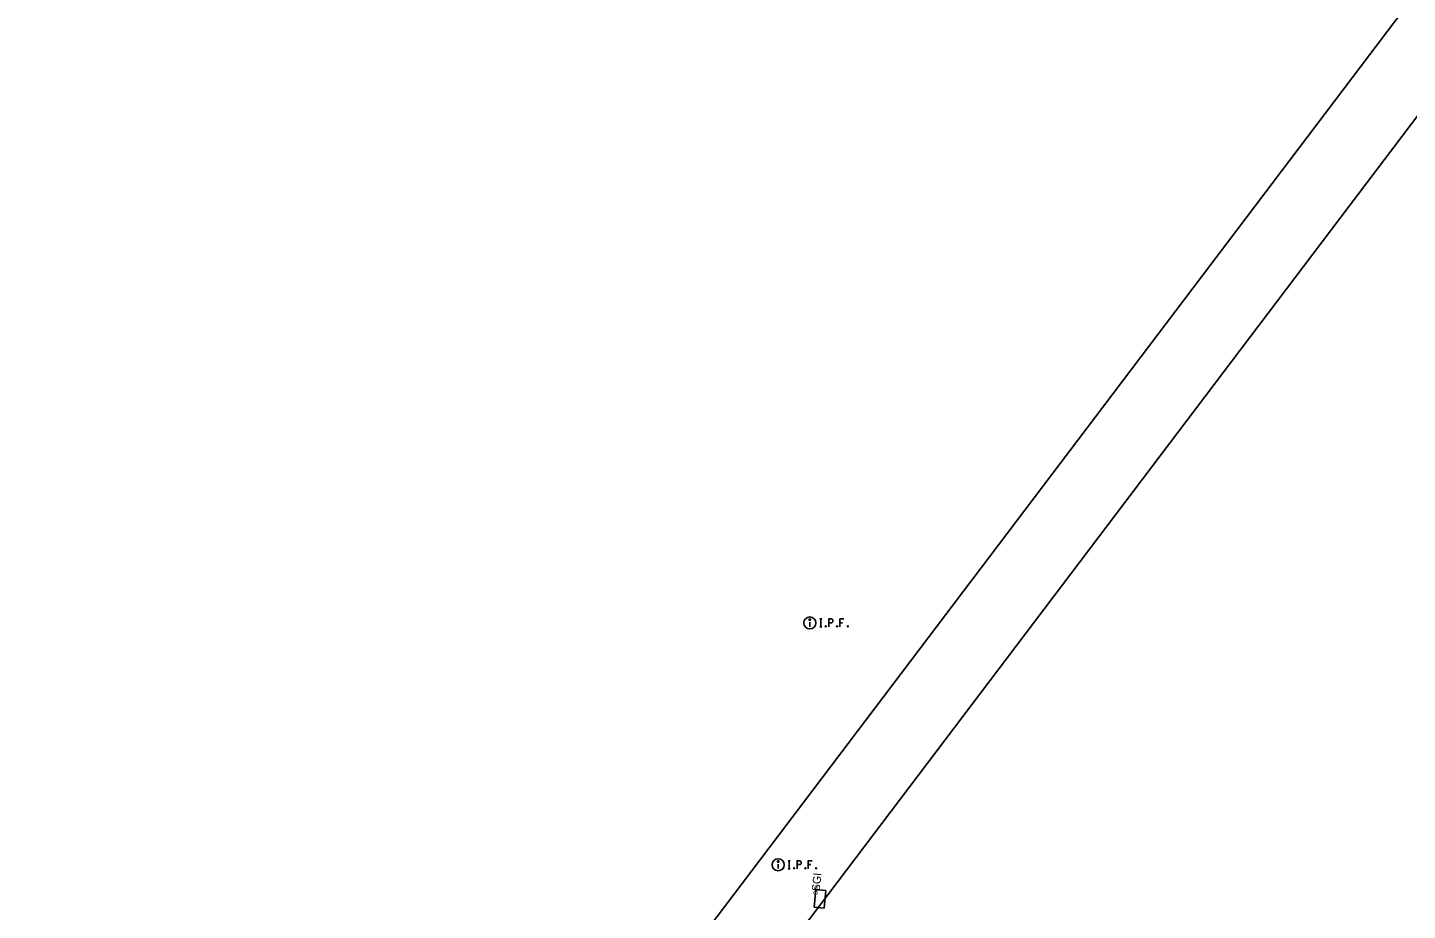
# Model space of a CAD drawing. Extents: x 1363693 to 1365209, y 422201 to 424153.
# Drawn here: x 1364113.8 to 1364389.7, y 423623 to 423799.5 of the extents above; entities that cross this region are included whole.
import ezdxf

# ---------------------------------------------------------------- set-up
doc = ezdxf.new("R2010")
doc.units = 0
for name, color, linetype in [('DR_X_Cells', 7, 'Continuous'), ('DR_X_Storm_Sewer', 7, 'Continuous'), ('DR_X_Text', 7, 'Continuous'), ('SV_X_Mon_Cells_Found', 7, 'Continuous')]:
    doc.layers.add(name, color=color, linetype=linetype)

msp = doc.modelspace()

# ---------------------------------------------------------------- linework, layer by layer
at = {"layer": 'DR_X_Cells'}
for p, q in [((1364271.04, 423623.65), (1364271.39, 423627.13)), ((1364271.04, 423623.65), (1364271.39, 423627.13)), ((1364273.38, 423626.93), (1364271.39, 423627.13)), ((1364273.38, 423626.93), (1364271.39, 423627.13)), ((1364273.38, 423626.93), (1364273.03, 423623.45)), ((1364273.38, 423626.93), (1364273.03, 423623.45)), ((1364271.04, 423623.65), (1364273.03, 423623.45)), ((1364271.04, 423623.65), (1364273.03, 423623.45))]:
    msp.add_line(p, q, dxfattribs=at)
at = {"layer": 'DR_X_Storm_Sewer'}
for p, q in [((1364653.56, 424152.81), (1364113.79, 423439.54)), ((1364665.52, 424143.76), (1364125.75, 423430.49))]:
    msp.add_line(p, q, dxfattribs=at)
at = {"layer": 'SV_X_Mon_Cells_Found'}
for p, q in [((1364270.18, 423680.58), (1364270.18, 423679.7)), ((1364263.85, 423632.21), (1364263.85, 423631.33))]:
    msp.add_line(p, q, dxfattribs=at)
for points in [[(1364272.21, 423681.26), (1364272.57, 423681.26)], [(1364272.21, 423679.66), (1364272.57, 423679.66)], [(1364272.39, 423679.66), (1364272.39, 423681.26)], [(1364273.35, 423679.88), (1364273.4, 423679.88), (1364273.44, 423679.85), (1364273.47, 423679.8), (1364273.47, 423679.74), (1364273.44, 423679.69), (1364273.4, 423679.66), (1364273.35, 423679.66), (1364273.32, 423679.69), (1364273.28, 423679.74), (1364273.28, 423679.8), (1364273.32, 423679.85), (1364273.35, 423679.88)], [(1364273.96, 423679.66), (1364273.96, 423681.26), (1364274.48, 423681.26), (1364274.54, 423681.25), (1364274.62, 423681.23), (1364274.65, 423681.2), (1364274.68, 423681.18), (1364274.73, 423681.11), (1364274.76, 423681.05), (1364274.78, 423680.95), (1364274.78, 423680.8), (1364274.77, 423680.75), (1364274.75, 423680.67), (1364274.71, 423680.58), (1364274.66, 423680.55), (1364274.63, 423680.52), (1364274.57, 423680.5), (1364274.48, 423680.48), (1364273.96, 423680.48)], [(1364275.6, 423679.88), (1364275.65, 423679.88), (1364275.69, 423679.85), (1364275.72, 423679.8), (1364275.72, 423679.74), (1364275.69, 423679.69), (1364275.65, 423679.66), (1364275.6, 423679.66), (1364275.57, 423679.69), (1364275.53, 423679.74), (1364275.53, 423679.8), (1364275.57, 423679.85), (1364275.6, 423679.88)], [(1364276.97, 423681.26), (1364276.2, 423681.26), (1364276.2, 423679.66)], [(1364276.2, 423680.48), (1364276.74, 423680.48)], [(1364277.75, 423679.88), (1364277.8, 423679.88), (1364277.84, 423679.85), (1364277.87, 423679.8), (1364277.87, 423679.74), (1364277.84, 423679.69), (1364277.8, 423679.66), (1364277.75, 423679.66), (1364277.71, 423679.69), (1364277.68, 423679.74), (1364277.68, 423679.8), (1364277.71, 423679.85), (1364277.75, 423679.88)], [(1364265.88, 423632.9), (1364266.23, 423632.9)], [(1364266.06, 423631.3), (1364266.06, 423632.9)], [(1364267.62, 423631.3), (1364267.62, 423632.9), (1364268.15, 423632.9), (1364268.2, 423632.89), (1364268.28, 423632.86), (1364268.32, 423632.83), (1364268.35, 423632.81), (1364268.39, 423632.75), (1364268.43, 423632.68), (1364268.45, 423632.58), (1364268.45, 423632.43), (1364268.44, 423632.38), (1364268.41, 423632.31), (1364268.37, 423632.22), (1364268.33, 423632.18), (1364268.29, 423632.15), (1364268.24, 423632.13), (1364268.15, 423632.12), (1364267.62, 423632.12)], [(1364270.63, 423632.9), (1364269.87, 423632.9), (1364269.87, 423631.3)], [(1364269.87, 423632.12), (1364270.41, 423632.12)], [(1364265.88, 423631.3), (1364266.23, 423631.3)], [(1364267.01, 423631.51), (1364267.07, 423631.51), (1364267.1, 423631.49), (1364267.14, 423631.44), (1364267.14, 423631.37), (1364267.1, 423631.32), (1364267.07, 423631.3), (1364267.01, 423631.3), (1364266.98, 423631.32), (1364266.95, 423631.37), (1364266.95, 423631.44), (1364266.98, 423631.49), (1364267.01, 423631.51)], [(1364269.26, 423631.51), (1364269.32, 423631.51), (1364269.35, 423631.49), (1364269.38, 423631.44), (1364269.38, 423631.37), (1364269.35, 423631.32), (1364269.32, 423631.3), (1364269.26, 423631.3), (1364269.23, 423631.32), (1364269.2, 423631.37), (1364269.2, 423631.44), (1364269.23, 423631.49), (1364269.26, 423631.51)], [(1364271.41, 423631.51), (1364271.47, 423631.51), (1364271.5, 423631.49), (1364271.53, 423631.44), (1364271.53, 423631.37), (1364271.5, 423631.32), (1364271.47, 423631.3), (1364271.41, 423631.3), (1364271.38, 423631.32), (1364271.35, 423631.37), (1364271.35, 423631.44), (1364271.38, 423631.49), (1364271.41, 423631.51)]]:
    msp.add_lwpolyline(points, dxfattribs=at)
for centre, radius in [((1364270.18, 423680.46), 1.2), ((1364270.18, 423681.12), 0.16), ((1364263.85, 423632.1), 1.2), ((1364263.85, 423632.75), 0.16)]:
    msp.add_circle(centre, radius, dxfattribs=at)

# ---------------------------------------------------------------- texts
at = {"layer": 'DR_X_Text'}
for height, p in [(1.6, (1364272.15, 423626.74)), (0.8, (1364271.68, 423626.06))]:
    msp.add_text('SGI', height=height, rotation=84.2528, dxfattribs=at).set_placement(p)

doc.saveas('drawing.dxf')
